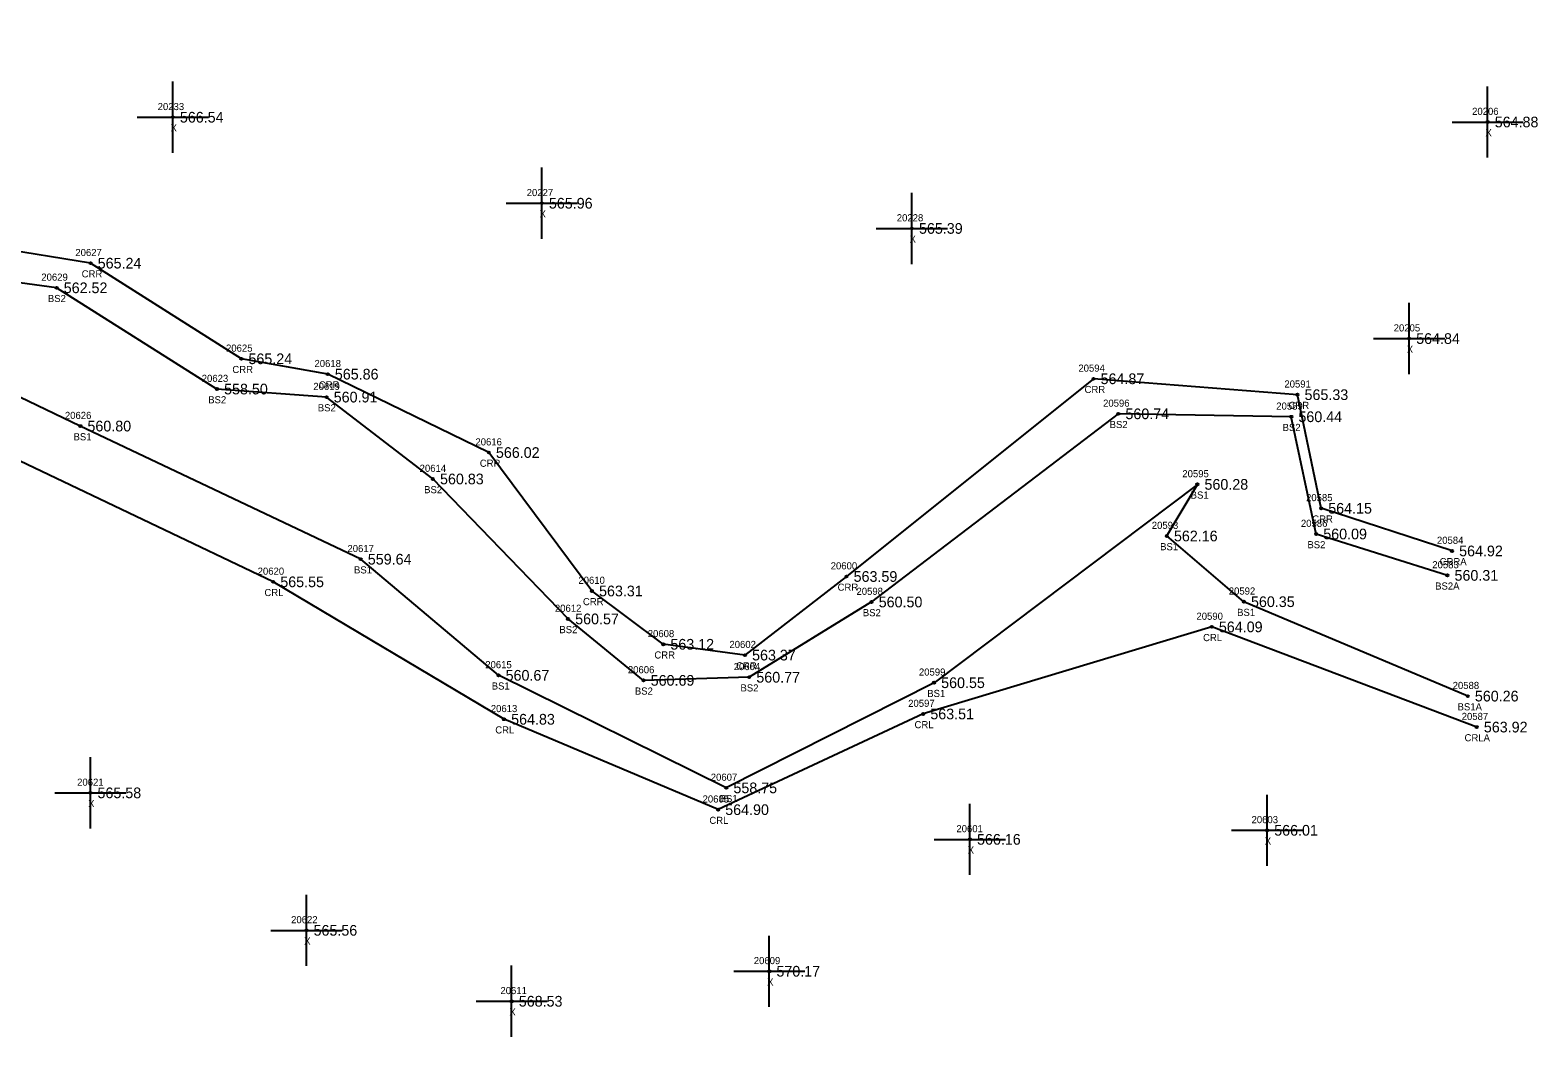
# Model space of a CAD drawing. Extents: x 1530159 to 1531652, y 877045 to 877724.
# Drawn here: x 1531149.1 to 1531360.8, y 877044.5 to 877186 of the extents above; entities that cross this region are included whole.
import ezdxf

# ---------------------------------------------------------------- set-up
doc = ezdxf.new("R2010")
doc.units = 0
for name, color, linetype in [('RD_DTM_BkLn2', 7, 'Continuous'), ('RD_DTM_BkLn_txCode', 7, 'Continuous'), ('RD_EX_H2O', 7, 'Continuous'), ('RD_EX_H2O_txCode', 7, 'Continuous'), ('RD_EX_Misc', 7, 'Continuous'), ('RD_EX_Misc_txCode', 7, 'Continuous'), ('RD_EX_TX_H2O_ELEV', 7, 'Continuous'), ('RD_EX_TX_Misc_ELEV', 7, 'Continuous'), ('RD_SMD_Locator', 7, 'Continuous')]:
    doc.layers.add(name, color=color, linetype=linetype)

msp = doc.modelspace()

# ---------------------------------------------------------------- linework, layer by layer
at = {"layer": 'RD_DTM_BkLn2'}
for points in [[(1531348.08, 877109.37), (1531329.65, 877115.18), (1531326.16, 877131.65), (1531301.87, 877132.06), (1531267.22, 877105.63), (1531250.04, 877095.06), (1531235.2, 877094.62), (1531224.6, 877103.25), (1531205.62, 877122.91), (1531190.69, 877134.41), (1531175.3, 877135.54), (1531152.78, 877149.76), (1531124.21, 877153.63), (1531078.42, 877140.23), (1531063.23, 877144), (1531046.52, 877162.43), (1531018.22, 877188.5), (1530969.53, 877218.21), (1530954.08, 877237.92), (1530933.73, 877250.44), (1530924.53, 877258.32), (1530897.88, 877293.87)], [(1531350.94, 877092.41), (1531319.5, 877105.67), (1531308.68, 877114.9), (1531312.97, 877122.15), (1531275.99, 877094.29), (1531246.82, 877079.52), (1531214.83, 877095.33), (1531195.48, 877111.64), (1531156.11, 877130.34), (1531140.38, 877137.85), (1531105.75, 877133.49), (1531075.68, 877125.77), (1531038.54, 877149.39), (1530993.41, 877183.7)]]:
    msp.add_lwpolyline(points, dxfattribs=at)
at = {"layer": 'RD_EX_H2O'}
for points in [[(1531348.73, 877112.8), (1531330.35, 877118.79), (1531327.02, 877134.75), (1531298.38, 877136.98), (1531263.7, 877109.21), (1531249.44, 877098.17), (1531237.97, 877099.69), (1531227.95, 877107.18), (1531213.47, 877126.62), (1531190.85, 877137.63), (1531178.72, 877139.79), (1531157.55, 877153.22), (1531117.73, 877159.68), (1531079.2, 877144.08), (1531065.91, 877145.46), (1531049.8, 877164.02), (1531030.35, 877191.82), (1530971.87, 877223.83), (1530957.12, 877241.36), (1530927.2, 877260.93), (1530922.5, 877289.86), (1530895.04, 877301.24)], [(1531352.2, 877088.06), (1531314.99, 877102.13), (1531274.47, 877089.9), (1531245.67, 877076.46), (1531215.61, 877089.16), (1531183.19, 877108.46), (1531131.31, 877133.17), (1531102.07, 877130.33), (1531078.17, 877119.78), (1531028.38, 877147.46), (1530991.55, 877179.5)]]:
    msp.add_lwpolyline(points, dxfattribs=at)
at = {"layer": 'RD_EX_Misc'}
for p, q in [((1531169.09, 877168.72), (1531169.09, 877178.72)), ((1531353.73, 877168.05), (1531353.73, 877178.05)), ((1531164.09, 877173.72), (1531174.09, 877173.72)), ((1531348.73, 877173.05), (1531358.73, 877173.05)), ((1531220.91, 877156.64), (1531220.91, 877166.64)), ((1531215.91, 877161.64), (1531225.91, 877161.64)), ((1531272.88, 877153.1), (1531272.88, 877163.1)), ((1531267.88, 877158.1), (1531277.88, 877158.1)), ((1531342.7, 877137.63), (1531342.7, 877147.63)), ((1531337.7, 877142.63), (1531347.7, 877142.63)), ((1531157.52, 877073.82), (1531157.52, 877083.82)), ((1531152.52, 877078.82), (1531162.52, 877078.82)), ((1531322.76, 877068.56), (1531322.76, 877078.56)), ((1531281.03, 877067.29), (1531281.03, 877077.29)), ((1531276.03, 877072.29), (1531286.03, 877072.29)), ((1531317.76, 877073.56), (1531327.76, 877073.56)), ((1531187.86, 877054.51), (1531187.86, 877064.51)), ((1531182.86, 877059.51), (1531192.86, 877059.51)), ((1531252.86, 877048.76), (1531252.86, 877058.76)), ((1531216.68, 877044.55), (1531216.68, 877054.55)), ((1531247.86, 877053.76), (1531257.86, 877053.76)), ((1531211.68, 877049.55), (1531221.68, 877049.55))]:
    msp.add_line(p, q, dxfattribs=at)
at = {"layer": 'RD_SMD_Locator'}
for centre in [(1531169.09, 877173.72), (1531353.73, 877173.05), (1531220.91, 877161.64), (1531272.88, 877158.1), (1531157.55, 877153.22), (1531152.78, 877149.76), (1531342.7, 877142.63), (1531178.72, 877139.79), (1531190.85, 877137.63), (1531298.38, 877136.98), (1531175.3, 877135.54), (1531190.69, 877134.41), (1531327.02, 877134.75), (1531301.87, 877132.06), (1531326.16, 877131.65), (1531156.11, 877130.34), (1531213.47, 877126.62), (1531205.62, 877122.91), (1531312.97, 877122.15), (1531330.35, 877118.79), (1531308.68, 877114.9), (1531329.65, 877115.18), (1531348.73, 877112.8), (1531195.48, 877111.64), (1531183.19, 877108.46), (1531263.7, 877109.21), (1531348.08, 877109.37), (1531227.95, 877107.18), (1531267.22, 877105.63), (1531319.5, 877105.67), (1531224.6, 877103.25), (1531314.99, 877102.13), (1531237.97, 877099.69), (1531249.44, 877098.17), (1531214.83, 877095.33), (1531235.2, 877094.62), (1531250.04, 877095.06), (1531275.99, 877094.29), (1531350.94, 877092.41), (1531215.61, 877089.16), (1531274.47, 877089.9), (1531352.2, 877088.06), (1531157.52, 877078.82), (1531246.82, 877079.52), (1531245.67, 877076.46), (1531281.03, 877072.29), (1531322.76, 877073.56), (1531187.86, 877059.51), (1531252.86, 877053.76), (1531216.68, 877049.55)]:
    msp.add_circle(centre, 0.15, dxfattribs=at)

# ---------------------------------------------------------------- texts
at = {"layer": 'RD_DTM_BkLn_txCode'}
for s, p in [('20629', (1531150.63, 877150.76)), ('BS2', (1531151.55, 877147.76)), ('20623', (1531173.16, 877136.54)), ('20619', (1531188.83, 877135.41)), ('BS2', (1531174.07, 877133.54)), ('20596', (1531299.73, 877133.06)), ('20589', (1531324.05, 877132.65)), ('20626', (1531153.94, 877131.34)), ('BS2', (1531189.46, 877132.41)), ('BS2', (1531300.65, 877130.06)), ('BS2', (1531324.94, 877129.65)), ('BS1', (1531155.16, 877128.34)), ('20614', (1531203.76, 877123.91)), ('20595', (1531310.86, 877123.15)), ('BS2', (1531204.39, 877120.91)), ('BS1', (1531312.03, 877120.15)), ('20593', (1531306.57, 877115.9)), ('20586', (1531327.51, 877116.18)), ('20617', (1531193.62, 877112.64)), ('BS1', (1531307.74, 877112.9)), ('BS2', (1531328.42, 877113.18)), ('BS1', (1531194.54, 877109.64)), ('20583', (1531345.96, 877110.37)), ('BS2A', (1531346.36, 877107.37)), ('20598', (1531265.1, 877106.63)), ('20592', (1531317.38, 877106.67)), ('20612', (1531222.75, 877104.25)), ('BS2', (1531265.99, 877103.63)), ('BS1', (1531318.55, 877103.67)), ('BS2', (1531223.38, 877101.25)), ('20615', (1531212.97, 877096.33)), ('20606', (1531233, 877095.62)), ('20604', (1531247.86, 877096.06)), ('20599', (1531273.87, 877095.29)), ('BS1', (1531213.88, 877093.33)), ('BS2', (1531233.98, 877092.62)), ('BS2', (1531248.81, 877093.06)), ('20588', (1531348.82, 877093.41)), ('BS1', (1531275.04, 877092.29)), ('BS1A', (1531349.51, 877090.41)), ('20607', (1531244.64, 877080.52)), ('BS1', (1531245.88, 877077.52))]:
    msp.add_text(s, height=1, dxfattribs=at).set_placement(p)
at = {"layer": 'RD_EX_H2O_txCode'}
for s, p in [('20627', (1531155.41, 877154.22)), ('CRR', (1531156.3, 877151.22)), ('20625', (1531176.57, 877140.79)), ('CRR', (1531177.46, 877137.79)), ('20618', (1531188.99, 877138.63)), ('20594', (1531296.26, 877137.98)), ('CRR', (1531189.6, 877135.63)), ('CRR', (1531297.13, 877134.98)), ('20591', (1531325.19, 877135.75)), ('CRR', (1531325.77, 877132.75)), ('20616', (1531211.59, 877127.62)), ('CRR', (1531212.21, 877124.62)), ('20585', (1531328.23, 877119.79)), ('CRR', (1531329.1, 877116.79)), ('20584', (1531346.61, 877113.8)), ('20620', (1531181.01, 877109.46)), ('20600', (1531261.48, 877110.21)), ('CRRA', (1531346.99, 877110.8)), ('20610', (1531226.05, 877108.18)), ('CRR', (1531262.45, 877107.21)), ('CRL', (1531181.96, 877106.46)), ('CRR', (1531226.69, 877105.18)), ('20590', (1531312.84, 877103.13)), ('20608', (1531235.79, 877100.69)), ('20602', (1531247.26, 877099.17)), ('CRL', (1531313.77, 877100.13)), ('CRR', (1531236.72, 877097.69)), ('CRR', (1531248.19, 877096.17)), ('20597', (1531272.36, 877090.9)), ('20613', (1531213.75, 877090.16)), ('20587', (1531350.09, 877089.06)), ('CRL', (1531214.38, 877087.16)), ('CRL', (1531273.25, 877087.9)), ('CRLA', (1531350.49, 877086.06)), ('20605', (1531243.49, 877077.46)), ('CRL', (1531244.44, 877074.46))]:
    msp.add_text(s, height=1, dxfattribs=at).set_placement(p)
at = {"layer": 'RD_EX_Misc_txCode'}
for s, p in [('20233', (1531166.97, 877174.72)), ('20206', (1531351.55, 877174.05)), ('X', (1531168.78, 877171.72)), ('X', (1531353.42, 877171.05)), ('20227', (1531218.79, 877162.64)), ('X', (1531220.6, 877159.64)), ('20228', (1531270.76, 877159.1)), ('X', (1531272.56, 877156.1)), ('20205', (1531340.54, 877143.63)), ('X', (1531342.38, 877140.63)), ('20621', (1531155.66, 877079.82)), ('X', (1531157.21, 877076.82)), ('20603', (1531320.58, 877074.56)), ('20601', (1531279.13, 877073.29)), ('X', (1531322.44, 877071.56)), ('X', (1531280.72, 877070.29)), ('20622', (1531185.71, 877060.51)), ('X', (1531187.54, 877057.51)), ('20609', (1531250.68, 877054.76)), ('20611', (1531215.1, 877050.55)), ('X', (1531252.55, 877051.76)), ('X', (1531216.36, 877047.55))]:
    msp.add_text(s, height=1, dxfattribs=at).set_placement(p)
at = {"layer": 'RD_EX_TX_H2O_ELEV'}
for s, p in [('565.24', (1531158.55, 877152.47)), ('565.24', (1531179.72, 877139.04)), ('565.86', (1531191.85, 877136.88)), ('564.87', (1531299.38, 877136.23)), ('565.33', (1531328.02, 877134)), ('566.02', (1531214.47, 877125.87)), ('564.15', (1531331.35, 877118.04)), ('564.92', (1531349.73, 877112.05)), ('565.55', (1531184.19, 877107.71)), ('563.59', (1531264.7, 877108.46)), ('563.31', (1531228.95, 877106.43)), ('564.09', (1531315.99, 877101.38)), ('563.12', (1531238.97, 877098.94)), ('563.37', (1531250.44, 877097.42)), ('564.83', (1531216.61, 877088.41)), ('563.51', (1531275.47, 877089.15)), ('563.92', (1531353.2, 877087.31)), ('564.90', (1531246.67, 877075.71))]:
    msp.add_text(s, height=1.5, dxfattribs=at).set_placement(p)
at = {"layer": 'RD_EX_TX_Misc_ELEV'}
for s, p in [('566.54', (1531170.09, 877172.97)), ('564.88', (1531354.73, 877172.3)), ('565.96', (1531221.91, 877160.89)), ('565.39', (1531273.88, 877157.35)), ('562.52', (1531153.78, 877149.01)), ('564.84', (1531343.7, 877141.88)), ('558.50', (1531176.3, 877134.79)), ('560.91', (1531191.69, 877133.66)), ('560.74', (1531302.87, 877131.31)), ('560.44', (1531327.16, 877130.9)), ('560.80', (1531157.11, 877129.59)), ('560.83', (1531206.62, 877122.16)), ('560.28', (1531313.97, 877121.4)), ('562.16', (1531309.68, 877114.15)), ('560.09', (1531330.65, 877114.43)), ('559.64', (1531196.48, 877110.89)), ('560.31', (1531349.08, 877108.62)), ('560.50', (1531268.22, 877104.88)), ('560.35', (1531320.5, 877104.92)), ('560.57', (1531225.6, 877102.5)), ('560.67', (1531215.83, 877094.58)), ('560.77', (1531251.04, 877094.31)), ('560.69', (1531236.2, 877093.87)), ('560.55', (1531276.99, 877093.54)), ('560.26', (1531351.94, 877091.66)), ('565.58', (1531158.52, 877078.07)), ('558.75', (1531247.82, 877078.77)), ('566.01', (1531323.76, 877072.81)), ('566.16', (1531282.03, 877071.54)), ('565.56', (1531188.86, 877058.76)), ('570.17', (1531253.86, 877053.01)), ('568.53', (1531217.68, 877048.8))]:
    msp.add_text(s, height=1.5, dxfattribs=at).set_placement(p)

doc.saveas('drawing.dxf')
